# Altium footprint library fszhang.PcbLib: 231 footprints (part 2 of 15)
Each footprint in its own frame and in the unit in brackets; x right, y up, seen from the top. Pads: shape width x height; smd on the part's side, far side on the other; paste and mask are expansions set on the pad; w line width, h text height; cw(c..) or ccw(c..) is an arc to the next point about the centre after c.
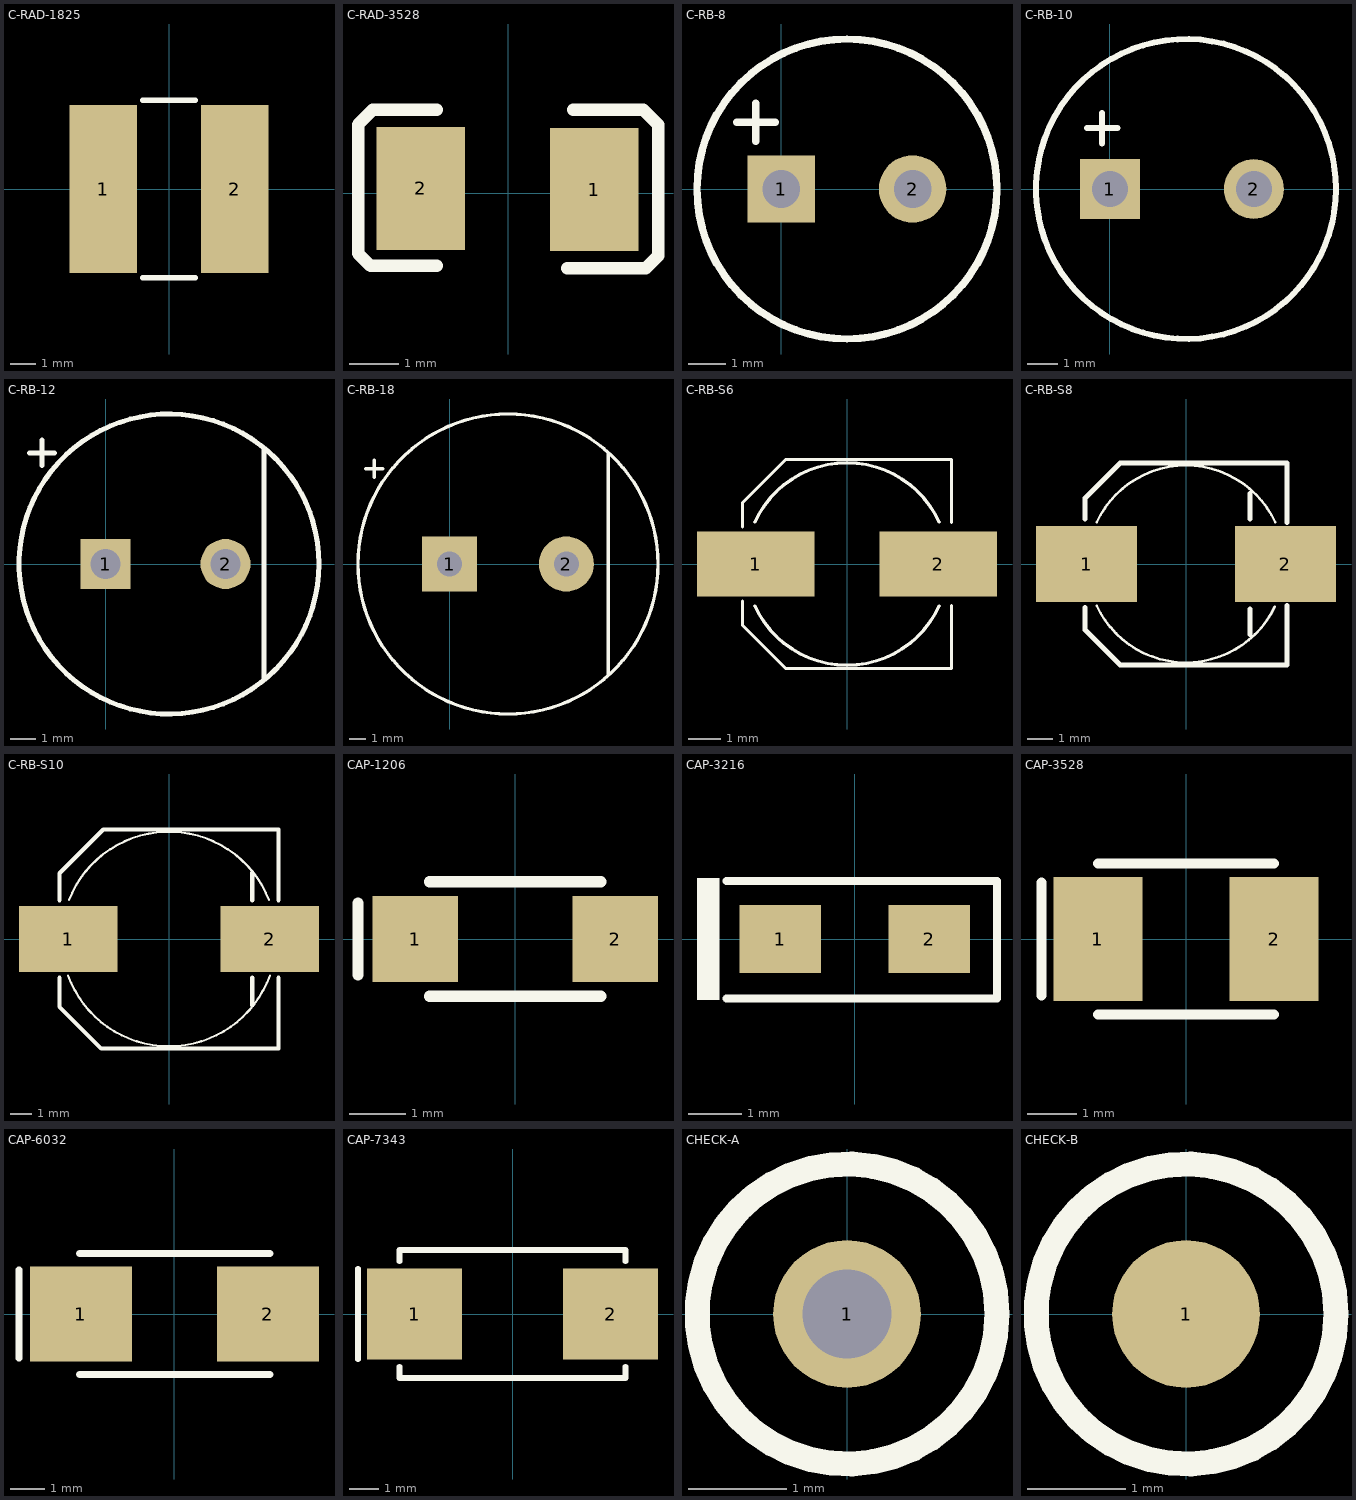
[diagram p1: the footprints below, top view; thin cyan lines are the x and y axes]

## C-RAD-1825 [mm] "贴片电阻"
pads (2):
  rect 2.6x6.5 smd: 1(-2.54,0) 2(2.54,0)
Top Overlay:
  lines w0.2: -1.016,-3.429 1.016,-3.429 ; -1.016,3.429 1.016,3.429
3D body: height 1.2, standoff 0, extent -2.286,-3.175 2.286,3.175

## C-RAD-3528 [mm] "贴片电容"
height 3
pads (2):
  rect 1.8x2.5 smd: 1(1.753,0.075) 2(-1.772,0.1)
Top Overlay:
  lines w0.254: -1.447,-1.475 -2.794,-1.475 -3.048,-1.221 -3.048,1.397 -2.745,1.7 -1.447,1.7 ; 1.203,-1.524 2.794,-1.524 3.048,-1.27 3.048,1.397 2.794,1.651 2.745,1.7 1.328,1.7

## C-RB-8 [mm] "35V 220UF电容"
height 12
pads (2):
  rect 1.8x1.8 hole 1: 1(0,0)
  round 1.8 hole 1: 2(3.5,0)
Top Overlay:
  circle w0.2: c1.75,0 r4
  lines w0.2: -1.185,1.778 -0.169,1.778 ; -0.677,1.27 -0.677,2.286

## C-RB-10 [mm] "35V470uF电容"
height 16
pads (2):
  rect 2x2 hole 1.2: 1(0,0)
  round 2 hole 1.2: 2(4.8,0)
Top Overlay:
  circle w0.2: c2.54,0 r5
  lines w0.2: -0.762,2.032 0.254,2.032 ; -0.254,1.524 -0.254,2.54

## C-RB-12 [mm] "35V470uF电容"
height 20
pads (2):
  rect 2x2 hole 1.2: 1(0,0)
  round 2 hole 1.2: 2(4.8,0)
Top Overlay:
  circle w0.2: c2.54,0 r6
  lines w0.2: -3.048,4.445 -2.032,4.445 ; -2.54,3.937 -2.54,4.953 ; 6.35,-4.572 6.35,4.572

## C-RB-18 [mm] "35V2200uF电容"
height 20
pads (2):
  rect 3.3x3.3 hole 1.5: 1(0,0)
  round 3.3 hole 1.5: 2(7,0)
Top Overlay:
  circle w0.2: c3.5,0 r9
  lines w0.2: -5.037,5.715 -4.021,5.715 ; -4.529,5.207 -4.529,6.223 ; 9.525,-6.604 9.525,6.604

## C-RB-S6 [mm] "贴片电解"
height 7
pads (2):
  rect 3.6x2 smd: 1(-2.794,0) 2(2.794,0)
Top Overlay:
  lines w0.1: -3.2,-1.143 -3.2,-1.88 -1.88,-3.2 3.2,-3.2 3.2,-1.27 ; -3.2,1.143 -3.2,1.88 -1.88,3.2 3.2,3.2 3.2,1.27 ; -2.822,-1.283 ccw(c0,0) 2.822,-1.283 ; -2.822,1.283 cw(c0,0) 2.822,1.283

## C-RB-S8 [mm] "贴片电解"
height 10.2
pads (2):
  rect 4x3 smd: 1(-3.937,0) 2(3.937,0)
Top Overlay:
  lines w0.1: -3.539,-1.643 ccw(c0,0) 3.516,-1.693 ; -3.539,1.643 cw(c0,0) 3.539,1.643
  lines w0.2: -4,-1.714 -4,-2.604 -2.604,-4 4,-4 4,-1.651 ; -4,1.778 -4,2.604 -2.604,4 4,4 4,1.651 ; 2.54,-2.794 2.54,-1.778 ; 2.54,1.778 2.54,2.794
3D body: height 10.9, standoff 0.9, extent -3.849,-3.872 3.88,3.872
3D body: height 0.6, standoff 0, extent -3.937,-3.937 3.937,3.937

## C-RB-S10 [mm] "贴片电解"
height 10.2
pads (2):
  rect 4.5x3 smd: 1(-4.6,0) 2(4.6,0)
Top Overlay:
  lines w0.1: -4.609,-1.664 ccw(c0,0) 4.609,-1.664 ; -4.567,1.776 cw(c0,0) 4.567,1.776
  lines w0.2: -5,-1.778 -5,-3.1 -3.1,-5 5,-5 5,-1.778 ; -5,1.778 -5,3 -3,5 5,5 5,1.778 ; 3.8,-3.032 3.8,-1.778 ; 3.8,1.778 3.8,3.032

## CAP-1206 [mil] "贴片元件"
height 59.06
pads (2):
  rect 60x60 smd: 1(-70,0) 2(70,0)
Top Overlay:
  lines w7.87: -110,-25 -110,25 ; -60,-40 60,-40 ; -60,40 60,40
3D body: height 39.37, standoff 0, extent -55,-35 55,35
3D body: height 39.37, standoff 0, extent 45,-35 65,35
3D body: height 39.37, standoff 0, extent -65,-35 -45,35

## CAP-3216 [mil] "钽电容"
height 78.74
pads (2):
  rect 60x50 smd: 1(-55,0) 2(55,0)
Top Overlay:
  region: -100,45 -116.46,45 -116.46,-45 -100,-45
  lines w5.91: -94.83,-43.92 105,-43.92 105,42.69 -94.83,42.69

## CAP-3528 [mm] "钽电容"
height 3
pads (2):
  rect 1.8x2.5 smd: 1(-1.778,0) 2(1.778,0)
Top Overlay:
  lines w0.2: -2.921,-1.143 -2.921,1.143 ; -1.778,1.524 1.778,1.524 ; -1.775,-1.524 1.778,-1.524
3D body: height 1.1, standoff 0, extent 1.524,-0.953 1.778,0.953
3D body: height 1, standoff 0, extent -1.905,-1.397 1.905,1.397

## CAP-6032 [mm] "钽电容"
pads (2):
  rect 3x2.8 smd: 1(-2.75,0) 2(2.75,0)
Top Overlay:
  lines w0.2: -4.572,-1.3 -4.572,1.3 ; -2.794,-1.778 2.806,-1.778 ; -2.794,1.778 2.806,1.778
3D body: height 1.3, standoff 0, extent -2.921,-1.651 2.921,1.651
3D body: height 1, standoff 0, extent -3.175,-1.143 -2.921,1.143
3D body: height 1, standoff 0, extent 2.921,-1.143 3.175,1.143

## CAP-7343 [mm] "钽电容"
height 4
pads (2):
  rect 3.2x3.05 smd: 1(-3.302,0) 2(3.302,0)
Top Overlay:
  lines w0.2: -5.207,-1.524 -5.207,1.524 ; -3.81,-1.778 -3.81,-2.159 3.81,-2.159 3.81,-1.778 ; -3.81,1.778 -3.81,2.159 3.81,2.159 3.81,1.778
3D body: height 1.3, standoff 0, extent 3.429,-1.143 3.683,1.143
3D body: height 1.3, standoff 0, extent -3.683,-1.143 -3.429,1.143
3D body: height 2.9, standoff 0, extent -3.429,-1.905 3.429,1.905
3D body: height 2.95, standoff 1.5, extent -3.429,-1.905 -2.921,1.905

## CHECK-A [mm] "Connector; Plug"
height 1.45
pads (1):
  round 1.5 hole 0.9: 1(0,0)
Top Overlay:
  circle w0.254: c0,0 r1.524

## CHECK-B [mm] "Connector; Plug"
height 1.45
pads (1):
  round 1.5 smd: 1(0,0)
Top Overlay:
  circle w0.254: c0,0 r1.524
